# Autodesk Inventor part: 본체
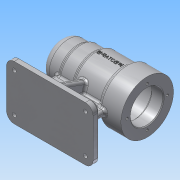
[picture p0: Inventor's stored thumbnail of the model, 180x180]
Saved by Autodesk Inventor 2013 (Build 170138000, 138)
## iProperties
Created: 2016-06
Part Number: 본체
Material: 알루미늄 6061
Document SubType Name: Modeling
Designer: Administrator
Density: 1 g/cm^3
Author: Administrator
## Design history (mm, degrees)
sketch "스케치1"
  geometry: L1 (-56, 0)-(56, 0); L2 (-56, 0)-(-56, 25); L3 (-56, 25)-(-31, 25); L4 (-31, 25)-(-31, 27); L5 (-31, 27)-(-11, 27); L6 (-11, 27)-(-11, 30); L7 (-11, 30)-(28, 30); L8 (28, 30)-(28, 34); L9 (28, 34)-(56, 34); L10 (56, 34)-(56, 0); 2 further points
  constraints: 20 end point, 6 parallel, 3 perpendicular, 1 coincident, 1 horizontal, 1 midpoint
  dimensions: "d0" = 112 distance of L1.start L1.end; "d1" = 50 diameter of L3 L1; "d2" = 54 diameter of L5 L1; "d3" = 60 diameter of L7 L1; "d4" = 68 diameter of L9 L1; "d5" = 25 distance of L3.end L2.end; "d6" = 45 horizontal distance of L5.end L2.end; "d7" = 84 horizontal distance of L7.end L2.end
revolve "회전1" sketch "스케치1" stored, may be unused: angle "d8" = 90 deg
sketch "스케치2"
  geometry: C1 r 34 at (0, 0) reference; C2 r 21 at (0, 0)
  constraints: 1 centre point, 1 coincident
  dimensions: "d9" = 42 diameter of C2
extrude "돌출1" cut sketch "스케치2" distance "d10" = 15; taper "d11" = 0 deg
hole "구멍1" diameter "d14" = 42; stored, may be unused: countersink angle "d18" = 90 deg, drill point angle "d20" = 0 deg; dims "d12" = 10, "d13" = 10, "d15" = 6, "d16" = 48, "d17" = 54, "d19" = 66
hole "구멍2" diameter "d23" = 32; stored, may be unused: countersink angle "d27" = 90 deg, drill point angle "d29" = 0 deg; dims "d21" = 10, "d22" = 10, "d24" = 6, "d25" = 35, "d26" = 18, "d28" = 22
sketch "스케치3"
  geometry: C1 r 16 at (0, 0) reference; C2 r 10.5 at (0, 0)
  constraints: 1 centre point, 1 coincident
  dimensions: "d30" = 21 diameter of C2
extrude "돌출2" cut sketch "스케치3" distance "d31" = 3; taper "d32" = 0 deg
fillet "모깎기1" dims "d33" = 10
fillet "모깎기2" dims "d34" = 3
sketch "스케치5"
  geometry: L1 (56, -60)-(-56, -60); L2 (-56, -60)-(-56, -70); L3 (-56, -70)-(56, -70); L4 (56, -70)-(56, -60); L5 (56, -60)-(-56, -70); L6 (-56, -60)-(56, -70); 3 further points
  constraints: 12 end point, 3 midpoint, 2 parallel, 1 horizontal, 1 perpendicular, 1 vertical alignment
  dimensions: "d35" = 112 distance of L3.end L2.end; "d36" = 10 distance of L2.end L1.end; "d37" = 70 distance from line of point (0, 0) L3
extrude "돌출3" join sketch "스케치5" stored distance "d38" = 70; taper "d39" = 0 deg; dims "d30" = 21
sketch "스케치6"
  geometry: C1 r 21 at (0, 0) reference; 1 further point
  constraints: 1 vertical alignment
  dimensions: "d40" = 26 distance of C1.centre point (0, 26)
hole "구멍3" sketch "스케치6" at (0, 26) diameter "d41" = 3.242; stored, may be unused: countersink angle "d45" = 90 deg, drill point angle "d47" = 118 deg; dims "d42" = 8, "d43" = 35, "d44" = 18, "d46" = 11
fillet "모깎기3" dims "d51" = 10
sketch "스케치8"
  geometry: A1 r 10 centre (0, 60) between (0, 70) and (-10, 60) reference; A2 r 10 centre (0, 10) between (-10, 10) and (0, 0) reference; A3 r 10 centre (92, 10) between (92, 0) and (102, 10) reference; A4 r 10 centre (92, 60) between (102, 60) and (92, 70) reference; 5 further points
  constraints: 4 coincident
hole "구멍4" sketch "스케치8" at (0, 60), (92, 60), (92, 10), (0, 10) diameter "d52" = 5; stored, may be unused: countersink angle "d56" = 90 deg, drill point angle "d58" = 0 deg; dims "d53" = 6, "d54" = 9, "d55" = 4, "d57" = 8
sketch "스케치9"
  geometry: L1 (-10, 60)-(-10, 10) reference; L2 (82, 31)-(10, 31); L3 (10, 31)-(10, 39); L4 (10, 39)-(82, 39); L5 (82, 39)-(82, 31); L6 (82, 31)-(10, 39); L7 (10, 31)-(82, 39); 1 further point
  constraints: 12 end point, 2 midpoint, 2 parallel, 1 horizontal, 1 perpendicular
  dimensions: "d59" = 8 distance of L2.end L3.end; "d60" = 20 distance between parallel lines of L1 L3
extrude "돌출4" join sketch "스케치9" stored distance "d61" = 10; taper "d62" = 0 deg
sketch "스케치10"
  geometry: L1 (-60, -35)-(-70, -35) reference; L2 (-70, -35)-(-70, 35) reference; L3 (-70, 35)-(-60, 35) reference; L4 (-60, 35)-(-60, 4) reference; L5 (-60, 4)-(-29.732, 4) reference; L6 (-29.732, -4)-(-60, -4) reference; L7 (-60, -4)-(-60, -35) reference; L8 (-60, 28)-(-25.68, 15.509); C1 r 24 at (0, 0) reference; A1 r 30 centre (0, 0) between (-29.732, -4) and (-29.732, 4) reference; 1 further point
  constraints: 2 end point, 1 point on circle, 1 point on line
  dimensions: "d63" = 7 distance of L3.end L8.start; "d64" = 110 deg angle of L4 L8
feature "리브1" sketch "스케치10" dims "d65" = 1, "d66" = 8, "d67" = 0, "d68" = 0, "d69" = 1, "d70" = 1
sketch "스케치12"
  geometry: L1 (-60, -4)-(-60, -35) reference; L2 (-60, -35)-(-70, -35) reference; L3 (-70, -35)-(-70, 35) reference; L4 (-70, 35)-(-60, 35) reference; L5 (-60, 35)-(-60, 28) reference; L6 (-60, 28)-(-25.68, 15.509) reference; L7 (-29.732, -4)-(-60, -4) reference; L8 (-25.68, -15.509)-(-60, -28); C1 r 24 at (0, 0) reference; A1 r 30 centre (0, 0) between (-29.732, -4) and (-25.68, 15.509) reference; 1 further point
  constraints: 2 end point, 1 point on circle, 1 point on line
  dimensions: "d71" = 7 distance of L1.end L8.end; "d72" = 110 deg angle of L1 L8
feature "리브2" sketch "스케치12" dims "d73" = 1, "d74" = 8, "d75" = 0, "d76" = 0, "d77" = 1, "d78" = 1
fillet "모깎기4" dims "d79" = 3
fillet "모깎기5" dims "d80" = 3
node "작업 평면1"
sketch "스케치13"
  geometry: L1 (47.5, -34)-(47.5, 34) reference; 2 further points
  constraints: 1 horizontal alignment, 1 other
  dimensions: "d81" = 48 distance from line of L1 point (-0.5, 0)
feature "엠보싱1" sketch "스케치13" dims "d12" = 10, "d13" = 10, "d82" = 0.5, "d83" = 0
fillet "모깎기6" dims "d84" = 3
fillet "모깎기7" dims "d85" = 3
chamfer "모따기1" distance "d86" = 1; stored, may be unused: second distance "d87" = 2, angle "d88" = 45 deg
fillet "모깎기8" dims "d89" = 0.3
chamfer "모따기2" distance "d90" = 4; stored, may be unused: second distance "d91" = 2, angle "d92" = 45 deg
node "솔리드1"
pattern_circular "원형 패턴1" dims angle "d49" = 360 deg
node "절단 모서리 투영1"
node "절단 모서리 투영2"
